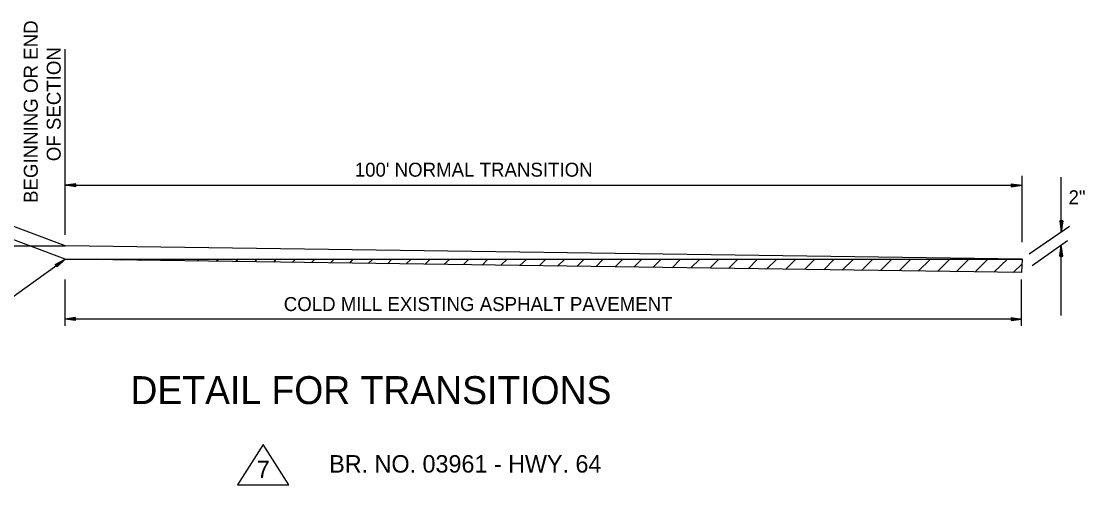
# Model space of a CAD drawing. Extents: x 1926836 to 1933254, y 596317 to 604524.
# Drawn here: x 1927553.6 to 1928011, y 600248.7 to 600447.8 of the extents above; entities that cross this region are included whole.
import ezdxf

# ---------------------------------------------------------------- set-up
doc = ezdxf.new("R2010")
doc.units = 0
doc.layers.add('Default', color=7, linetype='Continuous')
doc.layers.add('R_Annotation', color=7, linetype='Continuous')

msp = doc.modelspace()

# ---------------------------------------------------------------- linework, layer by layer
at = {"layer": 'Default'}
for p, q in [((1927572.43, 600356.03), (1927572.43, 600435.89)), ((1927983.99, 600352.93), (1927983.99, 600381.35)), ((1928000.86, 600357.36), (1928000.86, 600380.9)), ((1927577.1, 600378.02), (1927572.43, 600377.36)), ((1927572.43, 600377.36), (1927983.99, 600377.36)), ((1927577.1, 600376.7), (1927572.43, 600377.36)), ((1927577.1, 600377.81), (1927573.11, 600377.36)), ((1927577.1, 600376.7), (1927573.11, 600377.36)), ((1927577.1, 600377.81), (1927574, 600377.36)), ((1927577.1, 600376.92), (1927574, 600377.36)), ((1927577.1, 600377.58), (1927574.89, 600377.36)), ((1927577.1, 600376.92), (1927574.89, 600377.36)), ((1927577.1, 600377.58), (1927575.55, 600377.36)), ((1927577.1, 600377.14), (1927575.55, 600377.36)), ((1927577.1, 600377.36), (1927576.44, 600377.36)), ((1927577.1, 600377.14), (1927576.44, 600377.36)), ((1927577.1, 600376.7), (1927577.1, 600378.02)), ((1927979.32, 600378.02), (1927983.99, 600377.36)), ((1927979.32, 600378.02), (1927979.32, 600376.7)), ((1927979.32, 600377.81), (1927982.44, 600377.36)), ((1927979.32, 600377.81), (1927983.09, 600377.36)), ((1927979.32, 600377.58), (1927980.87, 600377.36)), ((1927979.32, 600377.58), (1927981.55, 600377.36)), ((1927979.32, 600376.7), (1927983.99, 600377.36)), ((1927979.32, 600377.14), (1927980.87, 600377.36)), ((1927979.32, 600376.92), (1927982.44, 600377.36)), ((1927979.32, 600376.7), (1927983.09, 600377.36)), ((1927979.32, 600376.92), (1927981.55, 600377.36)), ((1927979.32, 600377.14), (1927979.99, 600377.36)), ((1927979.32, 600377.36), (1927979.99, 600377.36)), ((1927572.43, 600351.37), (1927526.02, 600368.7)), ((1927572.43, 600345.6), (1927526.02, 600362.92)), ((1928000.2, 600362.03), (1928000.86, 600357.36)), ((1928001.53, 600362.03), (1928000.2, 600362.03)), ((1928000.43, 600362.03), (1928000.86, 600358.92)), ((1928000.43, 600362.03), (1928000.86, 600358.26)), ((1928000.63, 600362.03), (1928000.86, 600360.48)), ((1928000.63, 600362.03), (1928000.86, 600359.81)), ((1928001.53, 600362.03), (1928000.86, 600357.36)), ((1928001.08, 600362.03), (1928000.86, 600360.48)), ((1928001.31, 600362.03), (1928000.86, 600358.92)), ((1928001.53, 600362.03), (1928000.86, 600358.26)), ((1928001.31, 600362.03), (1928000.86, 600359.81)), ((1928000.86, 600362.03), (1928000.86, 600361.36)), ((1928001.08, 600362.03), (1928000.86, 600361.36)), ((1927987.1, 600347.83), (1928004.41, 600359.81)), ((1927988.42, 600342.94), (1928003.53, 600353.59)), ((1927456.96, 600351.37), (1927572.43, 600351.37)), ((1927983.99, 600345.6), (1927572.43, 600351.37)), ((1928000.2, 600346.93), (1928000.86, 600351.6)), ((1928000.43, 600346.93), (1928000.86, 600350.93)), ((1928000.43, 600346.93), (1928000.86, 600350.04)), ((1928000.63, 600346.93), (1928000.86, 600349.37)), ((1928000.63, 600346.93), (1928000.86, 600348.48)), ((1928000.86, 600321.39), (1928000.86, 600351.6)), ((1928001.53, 600346.93), (1928000.86, 600351.6)), ((1928001.53, 600346.93), (1928000.86, 600350.93)), ((1928001.31, 600346.93), (1928000.86, 600350.04)), ((1928001.31, 600346.93), (1928000.86, 600349.37)), ((1928001.08, 600346.93), (1928000.86, 600348.48)), ((1927543.13, 600324.51), (1927572.43, 600345.6)), ((1927568.22, 600343.37), (1927572.43, 600345.6)), ((1927568.45, 600343.37), (1927571.77, 600345.16)), ((1927568.45, 600343.37), (1927571.11, 600344.71)), ((1927568.45, 600343.15), (1927570.43, 600344.26)), ((1927568.45, 600343.15), (1927570, 600343.83)), ((1927568.88, 600342.48), (1927571.11, 600344.71)), ((1927568.88, 600342.72), (1927570.43, 600344.26)), ((1927568.88, 600342.72), (1927570, 600343.83)), ((1927569.1, 600342.27), (1927572.43, 600345.6)), ((1927569.1, 600342.48), (1927571.77, 600345.16)), ((1927983.76, 600339.82), (1927572.43, 600345.6)), ((1927572.43, 600345.6), (1927983.99, 600345.6)), ((1927588.64, 600345.37), (1927588.87, 600345.6)), ((1927596.75, 600345.26), (1927597.08, 600345.6)), ((1927604.86, 600345.15), (1927605.52, 600345.6)), ((1927613.17, 600345.03), (1927613.75, 600345.6)), ((1927621.29, 600344.91), (1927621.96, 600345.6)), ((1927629.39, 600344.8), (1927630.18, 600345.6)), ((1927637.5, 600344.69), (1927638.4, 600345.6)), ((1927645.8, 600344.57), (1927646.84, 600345.6)), ((1927653.91, 600344.46), (1927655.06, 600345.6)), ((1927662.23, 600344.34), (1927663.28, 600345.6)), ((1927670.13, 600344.23), (1927671.5, 600345.6)), ((1927678.45, 600344.11), (1927679.93, 600345.6)), ((1927686.55, 600344), (1927688.16, 600345.6)), ((1927694.86, 600343.88), (1927696.38, 600345.6)), ((1927702.74, 600343.77), (1927704.81, 600345.6)), ((1927711.09, 600343.66), (1927713.03, 600345.6)), ((1927719.19, 600343.54), (1927721.25, 600345.6)), ((1927727.3, 600343.41), (1927729.48, 600345.59)), ((1927735.4, 600343.31), (1927737.9, 600345.6)), ((1927743.72, 600343.2), (1927746.12, 600345.6)), ((1927751.82, 600343.08), (1927754.33, 600345.6)), ((1927759.92, 600342.97), (1927762.55, 600345.6)), ((1927768.02, 600342.86), (1927770.98, 600345.6)), ((1927776.35, 600342.74), (1927779.21, 600345.6)), ((1927784.22, 600342.62), (1927787.42, 600345.6)), ((1927792.56, 600342.51), (1927795.65, 600345.6)), ((1927800.88, 600342.39), (1927803.87, 600345.6)), ((1927808.98, 600342.27), (1927812.3, 600345.6)), ((1927817.09, 600342.16), (1927820.52, 600345.6)), ((1927825.2, 600342.05), (1927828.74, 600345.6)), ((1927833.53, 600341.93), (1927837.18, 600345.6)), ((1927841.63, 600341.82), (1927845.4, 600345.6)), ((1927849.73, 600341.7), (1927853.62, 600345.6)), ((1927857.82, 600341.59), (1927861.82, 600345.6)), ((1927866.15, 600341.47), (1927870.27, 600345.6)), ((1927874.04, 600341.36), (1927878.49, 600345.6)), ((1927882.36, 600341.25), (1927886.71, 600345.6)), ((1927890.47, 600341.13), (1927894.92, 600345.6)), ((1927898.78, 600341.02), (1927903.15, 600345.6)), ((1927906.66, 600340.9), (1927911.58, 600345.6)), ((1927914.98, 600340.79), (1927919.8, 600345.6)), ((1927923.14, 600340.71), (1927928.02, 600345.6)), ((1927931.2, 600340.56), (1927936.23, 600345.6)), ((1927939.3, 600340.45), (1927944.67, 600345.6)), ((1927947.62, 600340.33), (1927952.89, 600345.6)), ((1927955.73, 600340.21), (1927961.12, 600345.6)), ((1927963.84, 600340.1), (1927969.32, 600345.6)), ((1927971.93, 600339.99), (1927977.77, 600345.6)), ((1927983.99, 600345.6), (1927983.76, 600339.82)), ((1928000.2, 600346.93), (1928001.53, 600346.93)), ((1928001.08, 600346.93), (1928000.86, 600347.83)), ((1928000.86, 600346.93), (1928000.86, 600347.83)), ((1927568.22, 600343.37), (1927569.1, 600342.27)), ((1927568.67, 600342.94), (1927569.33, 600343.37)), ((1927568.67, 600342.94), (1927569.33, 600343.37)), ((1927980.25, 600339.86), (1927983.9, 600343.51)), ((1927572.43, 600316.94), (1927572.43, 600336.93)), ((1927983.76, 600316.94), (1927983.76, 600336.93)), ((1927576.89, 600320.5), (1927572.43, 600319.84)), ((1927576.89, 600320.5), (1927572.43, 600319.84)), ((1927983.76, 600319.84), (1927572.43, 600319.84)), ((1927576.89, 600319.17), (1927572.43, 600319.84)), ((1927576.89, 600319.17), (1927572.43, 600319.84)), ((1927576.89, 600320.5), (1927573.11, 600319.84)), ((1927576.89, 600320.5), (1927573.11, 600319.84)), ((1927576.89, 600319.39), (1927573.11, 600319.84)), ((1927576.89, 600319.39), (1927573.11, 600319.84)), ((1927576.89, 600320.29), (1927574, 600319.84)), ((1927576.89, 600320.29), (1927574, 600319.84)), ((1927576.89, 600319.39), (1927574, 600319.84)), ((1927576.89, 600319.39), (1927574, 600319.84)), ((1927576.89, 600320.29), (1927574.66, 600319.84)), ((1927576.89, 600320.29), (1927574.66, 600319.84)), ((1927576.89, 600319.61), (1927574.66, 600319.84)), ((1927576.89, 600319.61), (1927574.66, 600319.84)), ((1927576.89, 600320.05), (1927575.55, 600319.84)), ((1927576.89, 600320.05), (1927575.55, 600319.84)), ((1927576.89, 600319.61), (1927575.55, 600319.84)), ((1927576.89, 600319.61), (1927575.55, 600319.84)), ((1927576.89, 600320.05), (1927576.22, 600319.84)), ((1927576.89, 600320.05), (1927576.22, 600319.84)), ((1927576.89, 600319.84), (1927576.22, 600319.84)), ((1927576.89, 600319.84), (1927576.22, 600319.84)), ((1927576.89, 600319.17), (1927576.89, 600320.5)), ((1927576.89, 600319.17), (1927576.89, 600320.5)), ((1927979.32, 600320.5), (1927983.76, 600319.84)), ((1927979.32, 600320.5), (1927983.09, 600319.84)), ((1927979.32, 600320.5), (1927979.32, 600319.17)), ((1927979.32, 600320.29), (1927982.21, 600319.84)), ((1927979.32, 600320.29), (1927981.55, 600319.84)), ((1927979.32, 600320.05), (1927980.66, 600319.84)), ((1927979.32, 600320.05), (1927979.99, 600319.84)), ((1927979.32, 600319.17), (1927983.76, 600319.84)), ((1927979.32, 600319.61), (1927980.66, 600319.84)), ((1927979.32, 600319.39), (1927982.21, 600319.84)), ((1927979.32, 600319.39), (1927983.09, 600319.84)), ((1927979.32, 600319.61), (1927981.55, 600319.84)), ((1927979.32, 600319.84), (1927979.99, 600319.84))]:
    msp.add_line(p, q, dxfattribs=at)
at = {"layer": 'R_Annotation'}
for p, q in [((1927657.7, 600265.97), (1927646.66, 600248.67)), ((1927668.74, 600248.67), (1927657.7, 600265.97)), ((1927646.66, 600248.67), (1927668.74, 600248.67))]:
    msp.add_line(p, q, dxfattribs=at)

# ---------------------------------------------------------------- texts
at = {"layer": 'Default'}
for s, height, rotation, p in [('BEGINNING OR END', 6, 90, (1927560.7, 600369.76)), ('OF SECTION', 6, 90, (1927570.56, 600387.7)), ("100' NORMAL TRANSITION", 6, 360, (1927697.03, 600381.05)), ('2"', 6, 360, (1928003.99, 600369.2)), ('COLD MILL EXISTING ASPHALT PAVEMENT', 6, 360, (1927666.5, 600323.31)), ('DETAIL FOR TRANSITIONS', 12, 360, (1927600.57, 600283.32)), ('BR. NO. 03961 - HWY. 64', 7.5, 360, (1927686.05, 600253.88))]:
    msp.add_text(s, height=height, rotation=rotation, dxfattribs=at).set_placement(p)
at = {"layer": 'R_Annotation'}
msp.add_text('7', height=7.5, rotation=360, dxfattribs=at).set_placement((1927654.9, 600251.51))

doc.saveas('drawing.dxf')
